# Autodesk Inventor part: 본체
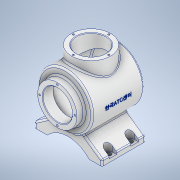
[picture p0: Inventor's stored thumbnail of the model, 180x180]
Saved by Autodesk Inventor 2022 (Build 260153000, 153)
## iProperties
Created: 2023-04
Part Number: 본체
Material: 알루미늄 6061
Document SubType Name: Modeling
Designer: ADMIN
Mass: 1270.2 g
Surface Area: 1063.56 cm^2
Volume: 470.446 cm^3
Density: 2.7 g/cm^3
Appearance: 알루미늄 - 평지
Author: ADMIN
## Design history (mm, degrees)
sketch "스케치1"
  geometry: L1 (62, 40)-(-62, 40); L2 (-62, 40)-(-62, -40); L3 (-62, -40)-(62, -40); L4 (62, -40)-(62, 40); L5 (86.8, 0)-(-86.8, 0) reference; L6 (0, -56)-(0, 56) reference; 1 further point
  constraints: 8 end point, 2 parallel, 1 horizontal, 1 perpendicular, 2 other
  dimensions: "d0" = 124 distance between parallel lines of L2 L4; "d1" = 80 distance of L3.end L1.start
extrude "돌출1" new body sketch "스케치1" distance "d2" = 10; taper "d3" = 0 deg
sketch "스케치2"
  geometry: L1 (77, 82.092)-(77, -72.441); L2 (-11.285, 0)-(67.711, 0) reference; L3 (0, -103.347)-(0, 112.998) reference; L4 (77, 60)-(113, 60); L5 (113, 60)-(113, 46); L6 (113, 46)-(77, 46); L7 (77, 46)-(77, 60); L8 (77, 46)-(127, 46); L9 (127, 46)-(127, -48.336); L10 (127, -48.336)-(77, -48.336); L11 (77, -48.336)-(77, 46); L12 (77, -48.336)-(77, -60); L13 (0, 40)-(10, 40) reference; A1 r 113 centre (77, 53) between (77, -60) and (127, -48.336); 2 further points
  constraints: 20 end point, 4 parallel, 2 horizontal, 2 perpendicular, 2 point on circle, 2 point on line, 1 centre point, 1 collinear, 1 midpoint, 1 vertical
  dimensions: "d4" = 77 distance between parallel lines of L3 L1; "d5" = 20 distance between parallel lines of L13 L4; "d6" = 120 distance from line of L12.end L4; "d94" = 113 radius of A1; "d95" = 100 diameter of L9 L1; "d96" = 72 diameter of L5 L1
revolve "회전1" sketch "스케치2" stored, may be unused: angle "d10" = 90 deg
sketch "스케치3"
  geometry: L1 (-62, 40)-(62, 40) reference; L2 (62, -40)-(-62, -40) reference; L3 (-25, 40)-(25, 40); L4 (25, 40)-(25, -40); L5 (25, -40)-(-25, -40); L6 (-25, -40)-(-25, 40); L7 (0, -84)-(0, 84) reference; 3 further points
  constraints: 8 end point, 2 parallel, 2 point on line, 1 horizontal, 1 perpendicular, 1 other
  dimensions: "d11" = 50 distance between parallel lines of L4 L6
extrude "돌출2" join sketch "스케치3" stored distance "d12" = 10; taper "d13" = 0 deg
sketch "스케치4"
  geometry: L1 (-62, 0)-(-62, 10) reference; L2 (-62, 10)-(-13.609, 43.883); 1 further point
  constraints: 2 end point
  dimensions: "d14" = 55 deg angle of L1 L2
feature "리브1" sketch "스케치4" dims "d15" = 1, "d16" = 80, "d17" = 0, "d18" = 0, "d19" = 1, "d20" = 1
sketch "스케치5"
  geometry: L1 (62, 0)-(62, 10) reference; L2 (62, 10)-(3.303, 51.1); 1 further point
  constraints: 2 end point
  dimensions: "d21" = 55 deg angle of L1 L2
feature "리브2" sketch "스케치5" dims "d22" = 1, "d23" = 80, "d24" = 0, "d25" = 0, "d26" = 1, "d27" = 1
sketch "스케치6"
  geometry: L1 (77, 132.344)-(77, -124.125); L2 (-25.4, 0)-(152.4, 0) reference; L3 (0, -175.418)-(0, 183.638) reference; L4 (41, 60)-(113, 60) reference; L5 (77, 60)-(104, 60); L6 (104, 60)-(104, 41); L7 (104, 41)-(77, 41); L8 (77, 41)-(77, 60); L9 (77, 41)-(120, 41); L10 (120, 41)-(120, -44.499); L11 (120, -44.499)-(77, -44.499); L12 (77, -44.499)-(77, 41); L13 (77, -44.499)-(77, -53); A1 r 113 centre (77, 60) between (77, -53) and (120, -44.499); 3 further points
  constraints: 20 end point, 4 parallel, 2 horizontal, 2 perpendicular, 2 point on circle, 2 point on line, 1 centre point, 1 midpoint, 1 vertical
  dimensions: "d28" = 77 distance between parallel lines of L3 L1; "d29" = 113 distance from line of L13.end L5; "d30" = 54 diameter of L6 L1; "d31" = 86 diameter of L10 L1; "d32" = 19 distance of L5.end L6.end; "d33" = 113 radius of A1
revolve "회전2" sketch "스케치6" stored, may be unused: angle "d34" = 360 deg
node "작업 평면1"
sketch "스케치7"
  geometry: L1 (0, -84)-(0, 84) reference; L2 (-36, 60)-(36, 60) reference; C1 r 36 at (0, -2); 1 further point
  constraints: 1 centre point, 1 point on line
  dimensions: "d36" = 72 diameter of C1; "d37" = 62 distance from line of L2 C1.centre
extrude "돌출3" join sketch "스케치7" stored distance "d38" = 10; taper "d39" = 0 deg
sketch "스케치8"
  geometry: C1 r 36 at (0, 0) reference; C2 r 27 at (0, 0); 1 further point
  constraints: 1 centre point, 1 coincident
  dimensions: "d40" = 54 diameter of C2
extrude "돌출4" cut sketch "스케치8" stored distance "d41" = 10; taper "d42" = 0 deg
sketch "스케치9"
  geometry: L1 (0, 0)-(124, 0) reference; L2 (23.5, 0)-(100.5, 0); L3 (62, 17)-(62, 0); L4 (62, 77)-(62, -57.516); C1 r 27 at (62, 77) reference; A1 r 52.096 centre (62, -35.096) between (100.5, 0) and (23.5, 0); 1 further point
  constraints: 6 end point, 3 point on circle, 1 centre point, 1 horizontal, 1 point on line, 1 symmetric about line, 1 vertical
  dimensions: "d43" = 17 distance of L3.start L3.end; "d44" = 77 distance of L2.start L2.end
extrude "돌출5" cut sketch "스케치9" extent not by distance; stored distance "d45" = 0; taper "d46" = 0 deg
node "작업 평면2"
sketch "스케치10"
  geometry: L1 (-36, 61.168)-(36, 61.168) reference; L2 (-77, -82.832)-(-77, 85.168) reference; 2 further points
  constraints: 1 other
  dimensions: "d47" = 62 distance from line of L1 point (0, -0.832); "d48" = 77 distance from line of L2 point (0, -0.832)
feature "엠보싱1" sketch "스케치10" dims "d0" = 124, "d1" = 80, "d4" = 77, "d5" = 20, "d6" = 120, "d49" = 0.5, "d50" = 0, "d94" = 113, "d95" = 100, "d96" = 72
sketch "스케치11" dims "d51" = 65
  geometry: L1 (0, -102.4)-(0, 75.4) reference; C1 r 36 at (0, 0) reference; 3 further points
  constraints: 1 coincident, 1 point on line, 1 vertical alignment, 2 other
hole "구멍1" sketch "스케치11" at (0, 32.5) diameter "d52" = 3.242; stored, may be unused: countersink angle "d56" = 90 deg, drill point angle "d58" = 118 deg; dims "d53" = 8, "d54" = 14, "d55" = 24, "d57" = 10
sketch "스케치12" dims "d62" = 65
  geometry: L1 (0, 82)-(0, -86) reference; C1 r 27 at (0, 0) reference; 3 further points
  constraints: 1 coincident, 1 point on line, 1 vertical alignment, 2 other
hole "구멍2" sketch "스케치12" at (0, 32.5) diameter "d63" = 3.242; stored, may be unused: countersink angle "d67" = 90 deg, drill point angle "d69" = 118 deg; dims "d64" = 8, "d65" = 4, "d66" = 2, "d68" = 10
node "작업 평면3"
sketch "스케치13"
  geometry: L1 (54, -27)-(62, -27); L2 (62, -27)-(72.529, -27); L3 (62, -27)-(62, -13); L4 (62, -13)-(54, -13); L5 (62, -40)-(62, 40) reference; L6 (26.694, -40)-(62, -40) reference; A1 r 7 centre (54, -20) between (54, -27) and (54, -13); 1 further point
  constraints: 8 end point, 2 point on circle, 2 point on line, 2 tangent, 1 centre point, 1 horizontal, 1 vertical
  dimensions: "d74" = 14 distance between parallel lines of L4 L1; "d75" = 20 distance from line of L6 A1.centre; "d76" = 8 distance from line of A1.centre L3
extrude "돌출6" cut sketch "스케치13" distance "d77" = 24; taper "d78" = 0 deg
sketch "스케치14"
  geometry: L1 (-38.5, 40)-(-62, 40) reference; L2 (-62, 40)-(-62, -40) reference; 2 further points
  dimensions: "d79" = 20 distance from line of L1 point (-54, 20); "d80" = 8 distance from line of L2 point (-54, 20)
hole "구멍3" sketch "스케치14" at (-54, 20) diameter "d81" = 9; stored, may be unused: countersink angle "d85" = 90 deg, drill point angle "d87" = 0 deg; dims "d82" = 6, "d83" = 4, "d84" = 2, "d86" = 6
chamfer "모따기1" distance "d88" = 1; stored, may be unused: second distance "d89" = 2, angle "d90" = 45 deg
fillet "모깎기2" dims "d92" = 3
fillet "모깎기3" dims "d93" = 3
fillet "모깎기4" dims "d97" = 3
node "솔리드1"
pattern_circular "원형 패턴1" dims angle "d60" = 360 deg
pattern_circular "원형 패턴2" dims angle "d71" = 360 deg
mirror "미러1"
mirror "미러2"
feature "A9D066F2-1C7D-4E18-AEED-F7BC21143FA4" dims "d81" = 9, "d82" = 6, "d83" = 4, "d84" = 2, "d85" = 90 deg, "d86" = 6, "d87" = 0
other parameters: "d35" = 142
